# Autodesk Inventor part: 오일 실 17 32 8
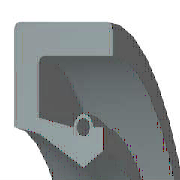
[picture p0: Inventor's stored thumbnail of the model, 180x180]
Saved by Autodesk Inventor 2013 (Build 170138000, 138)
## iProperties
IsCustomPart: 1
Created: 2012-02
Part Number: 오일 실 17 32 8
Material: 고무
Description: 오일-실
Document SubType Name: Modeling
Standard: KS B 2804
Designer: test
Standards Organization: KS
Language: ko-KR
Size Designation: S - 17 32 8
Categories: <MemberInstance><Categories><Category DisplayName="샤프트 부품" InternalName="7f7aeb1f-a693-4053-b835-cee3144e0d98" Mnemonic="SHFT"><Category DisplayName="실링" Intern
Density: 0.93 g/cm^3
Author: test
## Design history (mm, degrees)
revolve "본체" stored, may be unused: angle "d17" = 90 deg
revolve "스프링1" stored, may be unused: angle "d18" = 90 deg
body "Solid1"
sketch "스케치1"
  geometry: L1 (0, 16)-(8, 16); L2 (8, 16)-(8, 14.75); L3 (8, 14.75)-(1.75, 14.75); L4 (0, 16)-(0, 10.6); L5 (0, 10.6)-(1.75, 10.25); L6 (1.75, 10.25)-(4.9, 8.5); L7 (4.9, 8.5)-(0, 8.5); L8 (6.3, 9.375)-(6.3, 10.6); L9 (0, 0)-(9.586, 0) reference; L10 (4.9, 8.5)-(6.3, 9.375); L11 (0, 18)-(0, -3) reference; L12 (-1.917, 0)-(11.503, 0) reference; L13 (4.2, 10.6)-(1.75, 11.09); L14 (1.75, 11.09)-(1.75, 14.75); L15 (6.3, 10.6)-(5.6, 10.6); C1 r 0.455 at (4.9, 10.6); A1 r 0.7 centre (4.9, 10.6) between (5.6, 10.6) and (4.2, 10.6)
  constraints: 26 end point, 5 horizontal alignment, 4 perpendicular, 2 centre point, 2 collinear, 2 horizontal, 2 parallel, 2 point on circle, 2 point on line, 2 vertical alignment, 1 coincident
  dimensions: "d0" = 32 diameter of L1 L9 (= SD2); "d1" = 18.75 diameter of L8.start L9 (= ABDM); "d2" = 1.25 distance of L1.end L2.end (computed from SD); "d3" = 0.91 diameter of C1 (= SPDI); "d4" = 1.4 diameter of A1 (= SPDA); "d5" = 17 diameter of L6.end L9 (= NND); "d6" = 20.5 diameter of L5.end L9 (= TKDM); "d7" = 21.2 diameter of L4.end L9 (= HLDM); "d8" = 4.9 distance from line of C1.centre L4 (= SPDST); "d9" = 6.3 distance between parallel lines of L8 L4 (= SDI); "d10" = 8 distance between parallel lines of L2 L4 (= SWDT); "d12" = 1.75 distance between parallel lines of L14 L4 (= SD)
fillet "모깎기1" dims "d11" = 0.3 (= RR)
other parameters: "SD2" = 32 [user parameter; used in 1 equation term], "SWDT" = 8 [user parameter; used in 1 equation term], "RR" = 0.3 [user parameter; used in 1 equation term], "SD" = 1.75 [user parameter; used in 2 equation terms], "NND" = 17 [user parameter; used in 1 equation term], "SPDA" = 1.4 [user parameter; used in 1 equation term], "SPDI" = 0.91 [user parameter; used in 1 equation term], "TKDM" = 20.5 [user parameter; used in 1 equation term], "HLDM" = 21.2 [user parameter; used in 1 equation term], "ABDM" = 18.75 [user parameter; used in 1 equation term], "SDI" = 6.3 [user parameter; used in 1 equation term], "SPDST" = 4.9 [user parameter; used in 1 equation term], "d13" = 0, "d14" = 0, "d15" = 0, "LAB" = 0.35 [user parameter]
